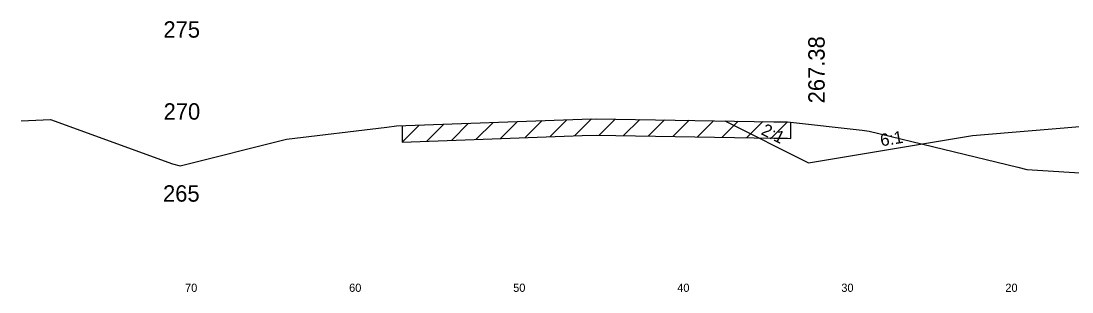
# Model space of a CAD drawing. Extents: x 1000 to 1162, y 999 to 8520.
# Drawn here: x 1000 to 1064.1, y 2539.5 to 2556 of the extents above; entities that cross this region are included whole.
import ezdxf

# ---------------------------------------------------------------- set-up
doc = ezdxf.new("R2010")
doc.units = 0
for name, color, linetype in [('Level 11', 7, 'Continuous'), ('Level 32', 7, 'Continuous'), ('Level 33', 7, 'Continuous'), ('Level 56', 7, 'Continuous'), ('Level 6', 7, 'Continuous'), ('Level 60', 7, 'Continuous'), ('Level 61', 7, 'Continuous'), ('Level 7', 7, 'Continuous')]:
    doc.layers.add(name, color=color, linetype=linetype)

msp = doc.modelspace()

# ---------------------------------------------------------------- linework, layer by layer
at = {"layer": 'Level 6'}
msp.add_line((1058, 2549.042), (1066, 2549.709), dxfattribs=at)
at = {"layer": 'Level 60'}
for p, q in [((1000, 2549.923), (1001.792, 2550)), ((1001.792, 2550), (1009.229, 2547.304)), ((1022.306, 2549.538), (1022.887, 2549.615)), ((1022.887, 2549.615), (1034.208, 2550.033)), ((1034.208, 2550.033), (1035.05, 2550.052)), ((1035.05, 2550.052), (1045.884, 2549.876)), ((1045.884, 2549.876), (1046.719, 2549.871)), ((1046.719, 2549.871), (1051.261, 2549.35)), ((1016.177, 2548.803), (1022.306, 2549.538)), ((1051.261, 2549.35), (1051.701, 2549.295)), ((1051.701, 2549.295), (1060.757, 2547.103)), ((1009.708, 2547.189), (1016.177, 2548.803)), ((1009.229, 2547.304), (1009.708, 2547.189)), ((1060.757, 2547.103), (1061.316, 2546.959)), ((1061.316, 2546.959), (1080, 2545.758))]:
    msp.add_line(p, q, dxfattribs=at)
at = {"layer": 'Level 61'}
for p, q in [((1024.271, 2549.666), (1023.232, 2548.628)), ((1023.232, 2549.628), (1023.232, 2548.628)), ((1025.771, 2549.722), (1024.732, 2548.683)), ((1027.271, 2549.777), (1026.232, 2548.739)), ((1028.771, 2549.832), (1027.732, 2548.794)), ((1030.271, 2549.888), (1029.232, 2548.849)), ((1031.771, 2549.943), (1030.732, 2548.905)), ((1033.271, 2549.998), (1032.232, 2548.96)), ((1034.763, 2550.046), (1033.732, 2549.016)), ((1036.216, 2550.033), (1035.232, 2549.049)), ((1037.716, 2550.009), (1036.732, 2549.025)), ((1039.216, 2549.984), (1038.232, 2549)), ((1040.716, 2549.96), (1039.732, 2548.976)), ((1042.216, 2549.935), (1041.232, 2548.952)), ((1043.716, 2549.911), (1042.732, 2548.927)), ((1045.216, 2549.887), (1044.232, 2548.903)), ((1046.724, 2549.87), (1045.732, 2548.878)), ((1046.929, 2548.847), (1046.929, 2549.847)), ((1023.232, 2548.628), (1034.208, 2549.033)), ((1034.208, 2549.033), (1035.05, 2549.052)), ((1035.05, 2549.052), (1045.884, 2548.876)), ((1045.884, 2548.876), (1046.719, 2548.871)), ((1046.719, 2548.871), (1046.929, 2548.847))]:
    msp.add_line(p, q, dxfattribs=at)
at = {"layer": 'Level 7'}
for p, q in [((1042.903, 2549.924), (1048, 2547.376)), ((1048, 2547.376), (1058, 2549.042))]:
    msp.add_line(p, q, dxfattribs=at)

# ---------------------------------------------------------------- texts
at = {"layer": 'Level 11'}
for s, p in [(' 275', (1008.307, 2555)), (' 270', (1008.319, 2550)), (' 265', (1008.284, 2545))]:
    msp.add_text(s, height=1, dxfattribs=at).set_placement(p)
at = {"layer": 'Level 32'}
for s, rotation, p in [('2:1', 333.43495, (1045.056, 2549.127)), ('6:1', 9.46232, (1052.435, 2548.368))]:
    msp.add_text(s, height=0.75, rotation=rotation, dxfattribs=at).set_placement(p)
at = {"layer": 'Level 33'}
msp.add_text('267.38', height=1, rotation=90, dxfattribs=at).set_placement((1048.986, 2550.995))
at = {"layer": 'Level 56'}
for s, p in [('70', (1010, 2539.5)), ('60', (1020, 2539.5)), ('50', (1030, 2539.5)), ('40', (1040, 2539.5)), ('30', (1050, 2539.5)), ('20', (1060, 2539.5))]:
    msp.add_text(s, height=0.5, dxfattribs=at).set_placement(p)

doc.saveas('drawing.dxf')
